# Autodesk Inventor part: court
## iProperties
Created: 2008-01
Part Number: court
Document SubType Name: Modeling
Designer: gjp
Author: gjp
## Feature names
1. Extrusion1
2. Extrusion2
3. Extrusion3
4. Extrusion4
5. Miroir1 [Mirror]
